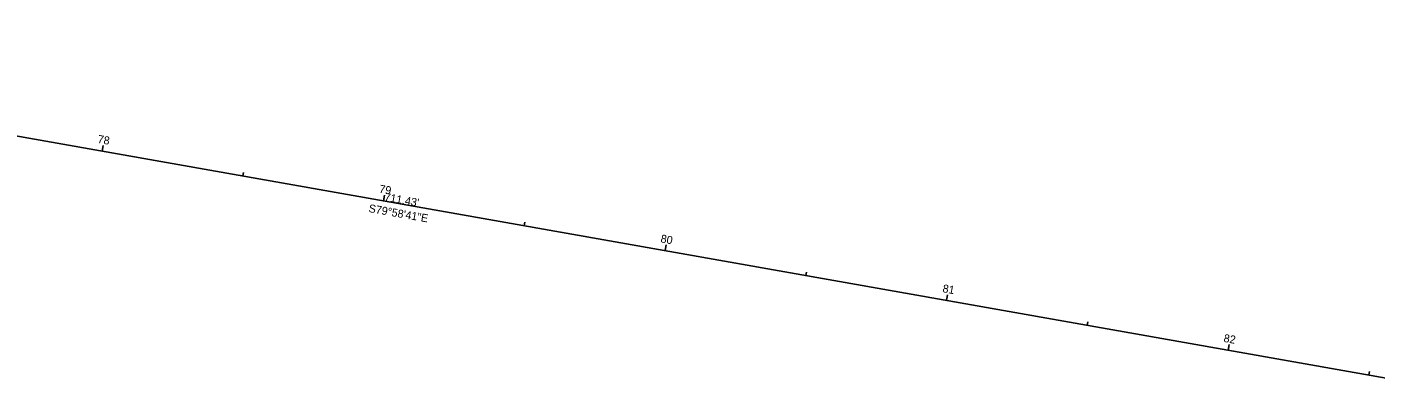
# Model space of a CAD drawing. Extents: x 1999336 to 2003366, y 252766 to 253936.
# Drawn here: x 2000486.4 to 2000958, y 253329.4 to 253453.2 of the extents above; entities that cross this region are included whole.
import ezdxf

# ---------------------------------------------------------------- set-up
doc = ezdxf.new("R2010")
doc.units = 0
for name, color, linetype in [('GE_X_CL_20', 7, 'Continuous'), ('GK_Visualization', 7, 'Continuous'), ('SC_Scratch3', 7, 'Continuous'), ('SV_X_Text_Name', 7, 'Continuous')]:
    doc.layers.add(name, color=color, linetype=linetype)

msp = doc.modelspace()

# ---------------------------------------------------------------- linework, layer by layer
at = {"layer": 'GE_X_CL_20'}
for p, q in [((2000512.71, 253409.79), (2000512.92, 253410.97)), ((2000611.19, 253392.39), (2000611.39, 253393.57)), ((2000709.66, 253374.99), (2000710.01, 253376.96)), ((2000808.13, 253357.59), (2000808.34, 253358.77)), ((2000906.61, 253340.18), (2000906.82, 253341.36))]:
    msp.add_line(p, q, dxfattribs=at)
at = {"layer": 'GK_Visualization'}
msp.add_line((2000267.25, 253453.17), (2000967.83, 253329.36), dxfattribs=at)
at = {"layer": 'SC_Scratch3'}
for p, q in [((2000512.71, 253409.79), (2000513.06, 253411.76)), ((2000561.95, 253401.09), (2000562.16, 253402.27)), ((2000611.19, 253392.39), (2000611.53, 253394.36)), ((2000660.42, 253383.69), (2000660.63, 253384.87)), ((2000709.66, 253374.99), (2000710.01, 253376.96)), ((2000758.9, 253366.29), (2000759.11, 253367.47)), ((2000808.13, 253357.59), (2000808.48, 253359.55)), ((2000857.37, 253348.88), (2000857.58, 253350.07)), ((2000906.61, 253340.18), (2000906.96, 253342.15)), ((2000955.85, 253331.48), (2000956.05, 253332.66))]:
    msp.add_line(p, q, dxfattribs=at)
at = {"layer": 'SV_X_Text_Name'}
msp.add_line((2000709.66, 253374.99), (2000710.01, 253376.96), dxfattribs=at)

# ---------------------------------------------------------------- texts
at = {"layer": 'GE_X_CL_20'}
for s, p in [("711.43'", (2000611.3, 253392.42)), ('S79°58\'41"E', (2000605.8, 253388.47)), ('80', (2000707.94, 253377.88))]:
    msp.add_text(s, height=2.8, rotation=349.9781, dxfattribs=at).set_placement(p)
at = {"layer": 'SC_Scratch3'}
for s, p in [('78', (2000511, 253412.68)), ('79', (2000609.5, 253395.27)), ("711.43'", (2000611.3, 253392.42)), ('S79°58\'41"E', (2000605.8, 253388.47)), ('80', (2000707.94, 253377.88)), ('81', (2000806.58, 253360.45)), ('82', (2000904.9, 253343.07))]:
    msp.add_text(s, height=2.8, rotation=349.9781, dxfattribs=at).set_placement(p)
at = {"layer": 'SV_X_Text_Name'}
for s, p in [("711.43'", (2000611.3, 253392.42)), ('S79°58\'41"E', (2000605.8, 253388.47)), ('80', (2000707.94, 253377.88))]:
    msp.add_text(s, height=2.8, rotation=349.9781, dxfattribs=at).set_placement(p)

doc.saveas('drawing.dxf')
